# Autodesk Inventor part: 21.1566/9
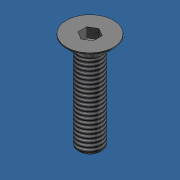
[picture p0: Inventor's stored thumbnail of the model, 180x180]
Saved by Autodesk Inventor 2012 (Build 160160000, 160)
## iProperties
Created: 2006-12
Part Number: 21.1566/9
Material: Steel, Mild
Description: M6X25 C'SUNK BLACK
Document SubType Name: Modeling
Standard: DIN 7991
Designer: Andy Moles
Standards Organization: DIN
Language: en-US
Size Designation: M6x20
Categories: <MemberInstance Version="R10.0.0"><Categories><Category DisplayName="Fasteners" InternalName="e4da775c-781d-43d5-af7c-5136215cf5a6" Mnemonic="FSTN"><Category Di
Density: 7.86 g/cm^3
Mass: 6.35538 g
Surface Area: 7.10236 cm^2
Volume: 0.808573 cm^3
Author: Andy Moles
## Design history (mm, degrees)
node "Sketch1"
node "WorkPoint1"
sketch "Sketch2"
  geometry: L1 (-3, -25)-(0, -25); L2 (-3, -3.3)-(-3, -25); L3 (-6, -0.3)-(-3, -3.3); L4 (-6, 0)-(-6, -0.3); L5 (0, 0)-(-6, 0); L6 (0, -25)-(0, 0); L7 (0, -25)-(0, 0); L8 (0, -22)-(0, 6) reference; L9 (0.6, 0)-(-7.8, 0) reference
  constraints: 14 end point, 3 vertical, 2 horizontal
  dimensions: "d1" = 45 deg angle of L3 L6; "d3" = 6 distance of L5.start L4.start (= 0.5 x dk); "d5" = 3 distance of L1.start L1.end (= 0.5 x NND); "d7" = 25 distance of L1.end L5.start (= NLG); "ParC" = 0.3 distance of L4.start L3.start; "d22" = 0 distance between parallel lines of L8 L6; "d23" = 0 distance between parallel lines of L9 L5
fillet "Fillet1" dims "d18" = 0.3 (= r)
chamfer "Chamfer1" distance "d19" = 0.5 (= 0.5 x PTC); stored, may be unused: angle "d20" = 45 deg, second distance "d39" = 0.5 (= 0.5 x PTC)
node "MSC_A1"
node "MSC_PF1"
node "MSC_PT1"
body "Solid1"
revolve "Revolution1" stored, may be unused: angle "d8" = 360 deg
sketch "Sketch3"
  geometry: L1 (-2, 1.155)-(-2, -1.155); L2 (0, 2.309)-(-2, 1.155); L3 (2, 1.155)-(0, 2.309); L4 (2, -1.155)-(2, 1.155); L5 (0, -2.309)-(2, -1.155); L6 (-2, -1.155)-(0, -2.309); C1 r 2 at (0, 0); C2 r 3 at (0, 0) reference
  constraints: 12 end point, 6 tangent, 2 parallel, 2 vertical, 1 centre point, 1 concentric
  dimensions: "d11" = 4 diameter of C1 (= ParS); "d13" = 120 deg angle of L1 L2; "d15" = 120 deg angle of L6 L1
extrude "Extrusion1" cut sketch "Sketch3" distance "d16" = 2.5 (= ParT); taper "d17" = 0 deg
thread "Thread1" dims "d35" = 0, "b" = 22
other parameters: "NND" = 6 [user parameter; used in 2 equation terms], "PTC" = 1 [user parameter; used in 2 equation terms], "dk" = 12 [user parameter; used in 1 equation term], "ParK" = 3.3 [user parameter], "ParS" = 4 [user parameter; used in 1 equation term], "ParT" = 2.5 [user parameter; used in 1 equation term], "r" = 0.3 [user parameter; used in 1 equation term], "NLG" = 25 [user parameter; used in 1 equation term], "d0" = 45 deg (derived), "d2" = 3 (derived), "d4" = 1.5 (derived), "d6" = 8 (derived), "d9" = 0, "d10" = 2 (derived), "d12" = 120 deg (derived), "d14" = 120 deg (derived), "d37" = 0, "d38" = 0, "d40" = 0, "d41" = 0, "d42" = 0, "THREADDIA" = 6 (= NND) [user parameter]
